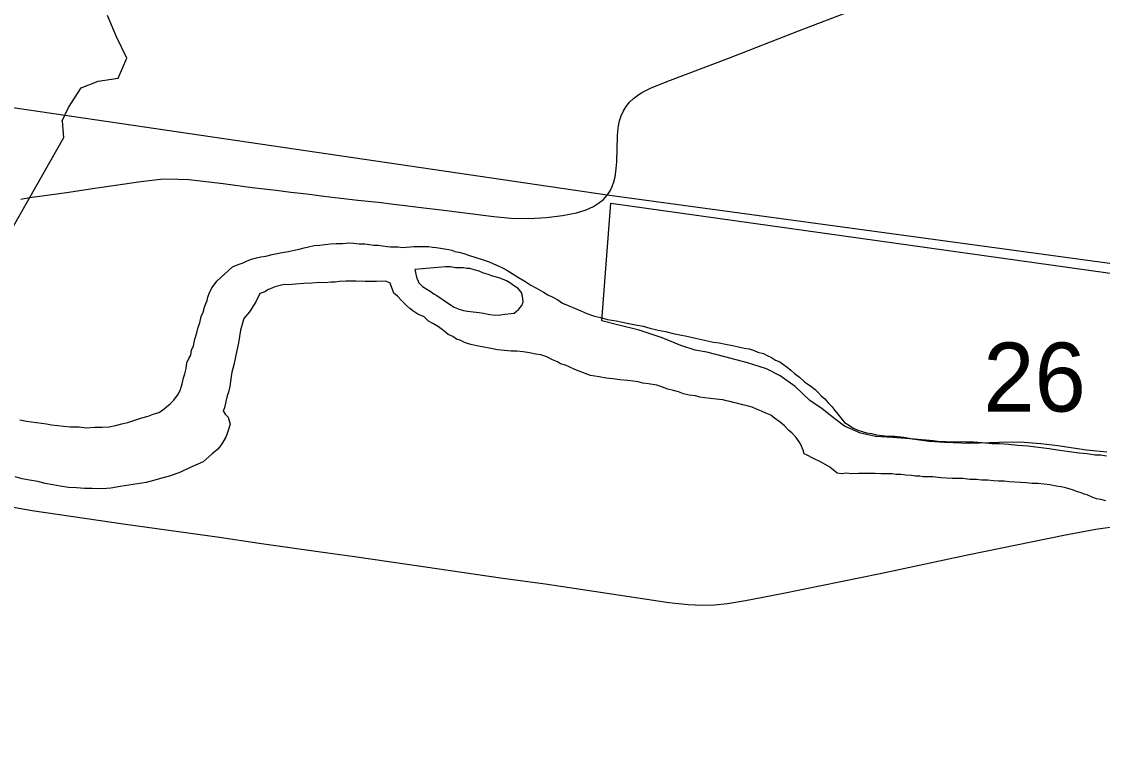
# Model space of a CAD drawing. Extents: x -19.5 to 44.1, y 0 to 22.
# Drawn here: x -18.261 to -17.606, y 7.214 to 7.66 of the extents above; entities that cross this region are included whole.
import ezdxf

# ---------------------------------------------------------------- set-up
doc = ezdxf.new("R2010")
doc.units = 0
for name, color, linetype in [('GM_X_Adjacent_County', 7, 'Continuous'), ('GM_X_Major_River', 7, 'Continuous'), ('GM_X_Minor_River', 7, 'Continuous'), ('GM_X_Section', 7, 'Continuous'), ('GM_X_Section_Text', 7, 'Continuous'), ('GM_X_Township_Road', 7, 'Continuous')]:
    doc.layers.add(name, color=color, linetype=linetype)

msp = doc.modelspace()

# ---------------------------------------------------------------- linework, layer by layer
at = {"layer": 'GM_X_Adjacent_County'}
msp.add_lwpolyline([(-18.50325, 7.6426), (-17.90583, 7.55487), (-17.11941, 7.4478), (-17.08323, 7.44316), (-15.5678, 7.21413)], dxfattribs=at)
at = {"layer": 'GM_X_Major_River'}
for points in [[(-18.1549, 7.47114), (-18.1541, 7.47455), (-18.15292, 7.4772), (-18.15212, 7.48099), (-18.15094, 7.48363), (-18.15015, 7.48666), (-18.14936, 7.48893), (-18.14858, 7.49082), (-18.14817, 7.49271), (-18.14738, 7.49498), (-18.14582, 7.49838), (-18.14428, 7.50026), (-18.14273, 7.50251), (-18.13313, 7.51112), (-18.1297, 7.51259), (-18.12665, 7.51368), (-18.12436, 7.51479), (-18.12169, 7.51589), (-18.11864, 7.51661), (-18.11597, 7.51733), (-18.11293, 7.51767), (-18.10912, 7.51875), (-18.10303, 7.5198), (-18.09923, 7.52051), (-18.0958, 7.52122), (-18.09275, 7.52194), (-18.08971, 7.52265), (-18.08704, 7.52337), (-18.08361, 7.52408), (-18.08019, 7.52441), (-18.07715, 7.52475), (-18.07373, 7.52508), (-18.07031, 7.52541), (-18.06651, 7.52536), (-18.06233, 7.52567), (-18.05967, 7.52564), (-18.05626, 7.52521), (-18.05285, 7.52515), (-18.05019, 7.52474), (-18.04754, 7.52432), (-18.04488, 7.52428), (-18.04223, 7.52386), (-18.0392, 7.52344), (-18.0373, 7.52341), (-18.03464, 7.52337), (-18.03275, 7.52334), (-18.03009, 7.52292), (-18.02325, 7.52359), (-18.02021, 7.52354), (-18.01756, 7.5235), (-18.01414, 7.52345), (-18.01187, 7.52304), (-18.00959, 7.52301), (-18.00694, 7.52259), (-18.00466, 7.52218), (-18.00201, 7.52176), (-18.00012, 7.52135), (-17.99823, 7.52056), (-17.99596, 7.52015), (-17.99293, 7.51934), (-17.98953, 7.51815), (-17.98613, 7.51697), (-17.98121, 7.51537), (-17.97743, 7.51418), (-17.97479, 7.513), (-17.97214, 7.51182), (-17.9695, 7.51064), (-17.96686, 7.50908), (-17.96347, 7.50713), (-17.9597, 7.50479), (-17.95593, 7.50246), (-17.95217, 7.50012), (-17.94877, 7.49817), (-17.94463, 7.49583), (-17.94199, 7.49427), (-17.93897, 7.49271), (-17.93595, 7.49115), (-17.93294, 7.4892), (-17.92954, 7.48763), (-17.92577, 7.48606), (-17.92199, 7.48448), (-17.91821, 7.4829), (-17.91368, 7.48132), (-17.90989, 7.48051), (-17.90573, 7.4793), (-17.90042, 7.47847), (-17.89664, 7.47765), (-17.89285, 7.47683), (-17.88869, 7.47601), (-17.88414, 7.47519), (-17.87998, 7.47399), (-17.87506, 7.47277), (-17.87051, 7.47195), (-17.86597, 7.47074), (-17.8618, 7.46992), (-17.85764, 7.4691), (-17.85234, 7.46788), (-17.84136, 7.46544), (-17.83795, 7.46501), (-17.83416, 7.4642), (-17.82999, 7.46338)], [(-18.00157, 7.4885), (-18.00054, 7.4879), (-17.99866, 7.48674), (-17.99563, 7.48555), (-17.99299, 7.48475), (-17.99071, 7.48434), (-17.9873, 7.48391), (-17.98351, 7.48348), (-17.98086, 7.48306), (-17.97707, 7.48224), (-17.97366, 7.48181), (-17.97062, 7.48215), (-17.96796, 7.48249), (-17.96416, 7.48281), (-17.96225, 7.48317), (-17.95957, 7.48541), (-17.95764, 7.48766), (-17.95685, 7.48993), (-17.95719, 7.49336), (-17.95792, 7.49565), (-17.96016, 7.49834), (-17.96205, 7.49951), (-17.96506, 7.50145), (-17.96694, 7.50262), (-17.97034, 7.50419), (-17.97299, 7.50499), (-17.97601, 7.50579), (-17.9779, 7.50658), (-17.98093, 7.50739), (-17.98357, 7.50856), (-17.9866, 7.50937), (-17.98925, 7.51017), (-17.99115, 7.51019), (-17.99304, 7.5106), (-17.99494, 7.51063), (-17.99798, 7.51068), (-18.00101, 7.5111), (-18.00404, 7.51114), (-18.02267, 7.50951)], [(-18.02267, 7.50951), (-18.02159, 7.50494), (-18.02011, 7.50149), (-18.01786, 7.49918), (-18.01523, 7.49762), (-18.01334, 7.49645), (-18.01108, 7.4949), (-18.0092, 7.49373), (-18.00157, 7.4885)], [(-18.08504, 7.5013), (-18.08998, 7.50099), (-18.09492, 7.50068), (-18.0991, 7.50036), (-18.10176, 7.5004), (-18.10518, 7.49969), (-18.10747, 7.49896), (-18.10938, 7.49823), (-18.11128, 7.4975), (-18.11358, 7.49601), (-18.11663, 7.49491), (-18.11897, 7.49001), (-18.12284, 7.48398), (-18.12631, 7.47985), (-18.1283, 7.47266), (-18.12954, 7.46507), (-18.13115, 7.45749), (-18.13236, 7.45181), (-18.13356, 7.44727), (-18.13397, 7.44461), (-18.13439, 7.44158), (-18.1348, 7.43854), (-18.13561, 7.43513), (-18.1364, 7.43286), (-18.1372, 7.42945), (-18.13801, 7.42566), (-18.13879, 7.42377), (-18.13767, 7.42186), (-18.1358, 7.41993), (-18.13471, 7.41573), (-18.1359, 7.41195), (-18.13709, 7.40817), (-18.13903, 7.40477), (-18.14057, 7.40251), (-18.14212, 7.40064), (-18.14557, 7.39765), (-18.15095, 7.39278), (-18.15896, 7.38948), (-18.1647, 7.38652), (-18.1708, 7.38433), (-18.17613, 7.38289), (-18.18108, 7.38144), (-18.18566, 7.38037), (-18.20125, 7.37793), (-18.20696, 7.37687), (-18.21228, 7.37657), (-18.21835, 7.37666), (-18.22291, 7.37672), (-18.22784, 7.37718), (-18.23277, 7.37725), (-18.2377, 7.37808), (-18.24225, 7.3789), (-18.24679, 7.37973), (-18.25133, 7.38094), (-18.25626, 7.38177), (-18.2608, 7.3826), (-18.26496, 7.38379)], [(-17.76073, 7.38596), (-17.76377, 7.38563), (-17.76642, 7.38605), (-17.77093, 7.38953), (-17.77621, 7.39265), (-17.78112, 7.395), (-17.78451, 7.39695), (-17.7864, 7.39774), (-17.78713, 7.40003), (-17.7886, 7.40385), (-17.79121, 7.40769), (-17.79383, 7.41039), (-17.79571, 7.41194), (-17.79833, 7.41464), (-17.80096, 7.41696), (-17.80435, 7.41929), (-17.8066, 7.42122), (-17.80963, 7.42241), (-17.81227, 7.42358), (-17.81529, 7.42477), (-17.81794, 7.42595), (-17.82096, 7.42675), (-17.82361, 7.42755), (-17.82664, 7.42836), (-17.82929, 7.42877), (-17.83156, 7.42957), (-17.83345, 7.42997), (-17.83572, 7.43039), (-17.83989, 7.43083), (-17.84331, 7.43126), (-17.84672, 7.43169), (-17.84975, 7.43211), (-17.8524, 7.43291), (-17.85619, 7.43335), (-17.8596, 7.43416), (-17.86262, 7.43534), (-17.86565, 7.43615), (-17.86905, 7.43696), (-17.87245, 7.43815), (-17.87586, 7.43933), (-17.88078, 7.44017), (-17.88419, 7.4406), (-17.88722, 7.4414), (-17.89025, 7.44183), (-17.89367, 7.44226), (-17.89822, 7.4427), (-17.90239, 7.44314), (-17.90656, 7.44358), (-17.91072, 7.4444), (-17.91338, 7.44482), (-17.91603, 7.44524), (-17.92359, 7.44801), (-17.92585, 7.44919), (-17.92849, 7.45037), (-17.93114, 7.45154), (-17.93416, 7.45235), (-17.93605, 7.45352), (-17.93907, 7.4547), (-17.94246, 7.45665), (-17.94624, 7.45785), (-17.94928, 7.45827), (-17.95306, 7.45908), (-17.95685, 7.45952), (-17.96065, 7.45996), (-17.96406, 7.46001), (-17.96823, 7.46045), (-17.9724, 7.46089), (-17.97657, 7.46171), (-17.98074, 7.46253), (-17.9849, 7.46335), (-17.98869, 7.46416), (-17.99058, 7.46457), (-17.99247, 7.46536), (-17.99473, 7.46653), (-17.99738, 7.46733), (-17.99964, 7.46889), (-18.00228, 7.47007), (-18.00491, 7.47238), (-18.0083, 7.47471), (-18.01131, 7.47666), (-18.01433, 7.47822), (-18.01695, 7.48092), (-18.02073, 7.4825), (-18.02374, 7.48444), (-18.02562, 7.48599), (-18.0275, 7.48754), (-18.0305, 7.49062), (-18.03312, 7.49332), (-18.03538, 7.49525), (-18.03758, 7.50137), (-18.04022, 7.50255), (-18.04592, 7.50225), (-18.05275, 7.50235), (-18.05845, 7.50243), (-18.06452, 7.50252), (-18.06832, 7.50219), (-18.07098, 7.50185), (-18.07364, 7.50189), (-18.07706, 7.50156), (-18.08048, 7.50161), (-18.08504, 7.5013)], [(-18.26225, 7.41835), (-18.25808, 7.41753), (-18.25505, 7.4171), (-18.25202, 7.41668), (-18.24899, 7.41625), (-18.24596, 7.41583), (-18.24293, 7.4154), (-18.23913, 7.41497), (-18.23572, 7.41454), (-18.23155, 7.4141), (-18.22624, 7.41402), (-18.22169, 7.41358), (-18.21675, 7.41389), (-18.21219, 7.41382), (-18.20801, 7.41414), (-18.20421, 7.41484), (-18.2004, 7.41593), (-18.19659, 7.41663), (-18.19239, 7.41809), (-18.1882, 7.41955), (-18.18439, 7.42064), (-18.18134, 7.42173), (-18.17791, 7.42282), (-18.17561, 7.42431), (-18.17331, 7.42618), (-18.17101, 7.42804), (-18.1687, 7.43029), (-18.166, 7.43405), (-18.16482, 7.4367), (-18.16364, 7.4401), (-18.16283, 7.44389), (-18.16205, 7.44616), (-18.16124, 7.44957), (-18.16082, 7.45298), (-18.15965, 7.45563), (-18.15849, 7.45751), (-18.15807, 7.46055), (-18.1569, 7.46319), (-18.15608, 7.46736), (-18.1549, 7.47114)], [(-17.82999, 7.46338), (-17.82621, 7.46256), (-17.8228, 7.46175), (-17.81977, 7.46133), (-17.81674, 7.46052), (-17.81448, 7.45935), (-17.81107, 7.45854), (-17.80881, 7.45737), (-17.80617, 7.45619), (-17.80391, 7.45463), (-17.80126, 7.45345), (-17.79901, 7.4519), (-17.79675, 7.45035), (-17.79449, 7.44841), (-17.79224, 7.44648), (-17.78923, 7.44415), (-17.78623, 7.44145), (-17.78247, 7.43874), (-17.77983, 7.43679), (-17.77796, 7.43487), (-17.77608, 7.43294), (-17.77383, 7.43101), (-17.77196, 7.4287), (-17.76971, 7.42639), (-17.76784, 7.42408), (-17.76597, 7.42177), (-17.76448, 7.41985), (-17.76186, 7.41677), (-17.75998, 7.4156), (-17.75659, 7.41327), (-17.75394, 7.41209), (-17.7513, 7.41129), (-17.74865, 7.41049), (-17.74562, 7.41007), (-17.74259, 7.40927), (-17.73918, 7.40883), (-17.73577, 7.4084), (-17.73159, 7.40834), (-17.7259, 7.40788), (-17.72174, 7.40706), (-17.71719, 7.40662), (-17.71264, 7.40617), (-17.70808, 7.40572), (-17.70391, 7.40528), (-17.7005, 7.40523), (-17.68835, 7.40505), (-17.6838, 7.40499), (-17.67849, 7.40453), (-17.67242, 7.40406), (-17.66786, 7.40399), (-17.66255, 7.40354), (-17.65686, 7.40307), (-17.65079, 7.40261), (-17.64435, 7.40175), (-17.63791, 7.4009), (-17.63146, 7.40004), (-17.6254, 7.39919), (-17.61971, 7.39835), (-17.61478, 7.3979), (-17.60986, 7.39707), (-17.60644, 7.39702), (-17.60303, 7.39659)], [(-17.60337, 7.36922), (-17.6064, 7.37003), (-17.60905, 7.37045), (-17.61132, 7.37124), (-17.61472, 7.37281), (-17.61661, 7.37322), (-17.6185, 7.37401), (-17.62115, 7.3748), (-17.62304, 7.37559), (-17.62569, 7.37639), (-17.62795, 7.37718), (-17.63061, 7.3776), (-17.63364, 7.37803), (-17.63742, 7.37884), (-17.64083, 7.37927), (-17.64463, 7.37971), (-17.64804, 7.37976), (-17.65183, 7.38019), (-17.66208, 7.38072), (-17.66511, 7.38115), (-17.66853, 7.3812), (-17.67156, 7.38124), (-17.67498, 7.38167), (-17.67877, 7.38173), (-17.6818, 7.38215), (-17.68408, 7.38219), (-17.68598, 7.38221), (-17.69015, 7.38265), (-17.6966, 7.38275), (-17.70343, 7.38323), (-17.70836, 7.38368), (-17.71178, 7.38373), (-17.71444, 7.38377), (-17.71633, 7.38418), (-17.71898, 7.38421), (-17.72126, 7.38463), (-17.72467, 7.38468), (-17.72771, 7.3851), (-17.73074, 7.38515), (-17.73302, 7.38556), (-17.73681, 7.38562), (-17.73985, 7.38566), (-17.74326, 7.38571), (-17.74706, 7.38576), (-17.75048, 7.38581), (-17.75351, 7.38586), (-17.75769, 7.38554), (-17.76073, 7.38596)]]:
    msp.add_lwpolyline(points, dxfattribs=at)
at = {"layer": 'GM_X_Minor_River'}
for points in [[(-18.23643, 7.59981), (-18.23273, 7.60779), (-18.22504, 7.61986), (-18.21477, 7.62393), (-18.20264, 7.6257), (-18.19722, 7.63779), (-18.20353, 7.65076), (-18.20908, 7.66372)], [(-18.23643, 7.59981), (-18.23576, 7.58944), (-18.27928, 7.5132), (-18.28963, 7.50771), (-18.32046, 7.50264), (-18.33306, 7.49425)]]:
    msp.add_lwpolyline(points, dxfattribs=at)
at = {"layer": 'GM_X_Section'}
msp.add_lwpolyline([(-17.60277, 7.39864), (-17.61525, 7.39996), (-17.63263, 7.40248), (-17.64284, 7.40376), (-17.6557, 7.40471), (-17.6682, 7.40451), (-17.68601, 7.40401), (-17.70114, 7.40461), (-17.7106, 7.40512), (-17.72232, 7.40681), (-17.73291, 7.40772), (-17.74313, 7.40824), (-17.75219, 7.41027), (-17.76197, 7.41458), (-17.76872, 7.4196), (-17.77545, 7.425), (-17.78295, 7.43003), (-17.79192, 7.43849), (-17.80091, 7.44506), (-17.80918, 7.44935), (-17.82087, 7.45293), (-17.83445, 7.45653), (-17.84539, 7.45934), (-17.85257, 7.46058), (-17.86124, 7.46336), (-17.87253, 7.46806), (-17.88647, 7.47281), (-17.89968, 7.47604), (-17.90911, 7.47844), (-17.90376, 7.54979), (-17.37709, 7.47609)], dxfattribs=at)
at = {"layer": 'GM_X_Township_Road'}
for points in [[(-17.90582, 7.55487), (-17.90415, 7.55737), (-17.9028, 7.56002), (-17.9018, 7.56283), (-17.90108, 7.56575), (-17.90059, 7.56874), (-17.90013, 7.57487), (-17.89973, 7.59045), (-17.89948, 7.5936), (-17.89904, 7.59675), (-17.89836, 7.59985), (-17.89735, 7.6029), (-17.89602, 7.60581), (-17.89436, 7.60854), (-17.89233, 7.61103), (-17.89005, 7.61325), (-17.88752, 7.6152), (-17.88483, 7.61689), (-17.87917, 7.61972), (-17.86756, 7.62437), (-17.83274, 7.63767), (-17.7893, 7.6545), (-17.74579, 7.67114)], [(-18.26153, 7.55232), (-18.25625, 7.55319), (-18.2457, 7.55467), (-18.23256, 7.55652), (-18.21812, 7.55864), (-18.18889, 7.56296), (-18.17527, 7.56456), (-18.16631, 7.56447), (-18.15965, 7.56411), (-18.13883, 7.56179), (-18.12134, 7.55938), (-18.10672, 7.55772), (-18.09783, 7.55652), (-18.08812, 7.5555), (-18.0777, 7.55413), (-18.05726, 7.55168), (-18.04881, 7.55077), (-18.04274, 7.55014), (-18.03704, 7.54949), (-18.0337, 7.54901), (-18.03008, 7.54863), (-18.01715, 7.54708), (-18.00669, 7.54569), (-17.99235, 7.54393), (-17.97475, 7.54181), (-17.96431, 7.54072), (-17.95321, 7.54052), (-17.94273, 7.5411), (-17.93293, 7.54231), (-17.92448, 7.54403), (-17.91862, 7.54579), (-17.91416, 7.5477), (-17.91111, 7.54976), (-17.90815, 7.55198), (-17.90582, 7.55487)], [(-18.28469, 7.36867), (-18.25471, 7.36342), (-18.1982, 7.35503), (-18.14098, 7.34707), (-18.11699, 7.34356), (-18.08132, 7.33853), (-18.05915, 7.33552), (-18.01612, 7.32915), (-17.97063, 7.32249), (-17.94354, 7.31879), (-17.89928, 7.31217), (-17.86857, 7.30757), (-17.85688, 7.30628), (-17.84827, 7.30586), (-17.84088, 7.30606), (-17.83291, 7.30684), (-17.82193, 7.30864), (-17.79998, 7.31289), (-17.74033, 7.32514), (-17.68625, 7.33673), (-17.62901, 7.34843), (-17.60942, 7.35199), (-17.59523, 7.35398)]]:
    msp.add_lwpolyline(points, dxfattribs=at)

# ---------------------------------------------------------------- texts
at = {"layer": 'GM_X_Section_Text'}
msp.add_text('26', height=0.041856, rotation=0.00001, dxfattribs=at).set_placement((-17.67783, 7.42336))

doc.saveas('drawing.dxf')
